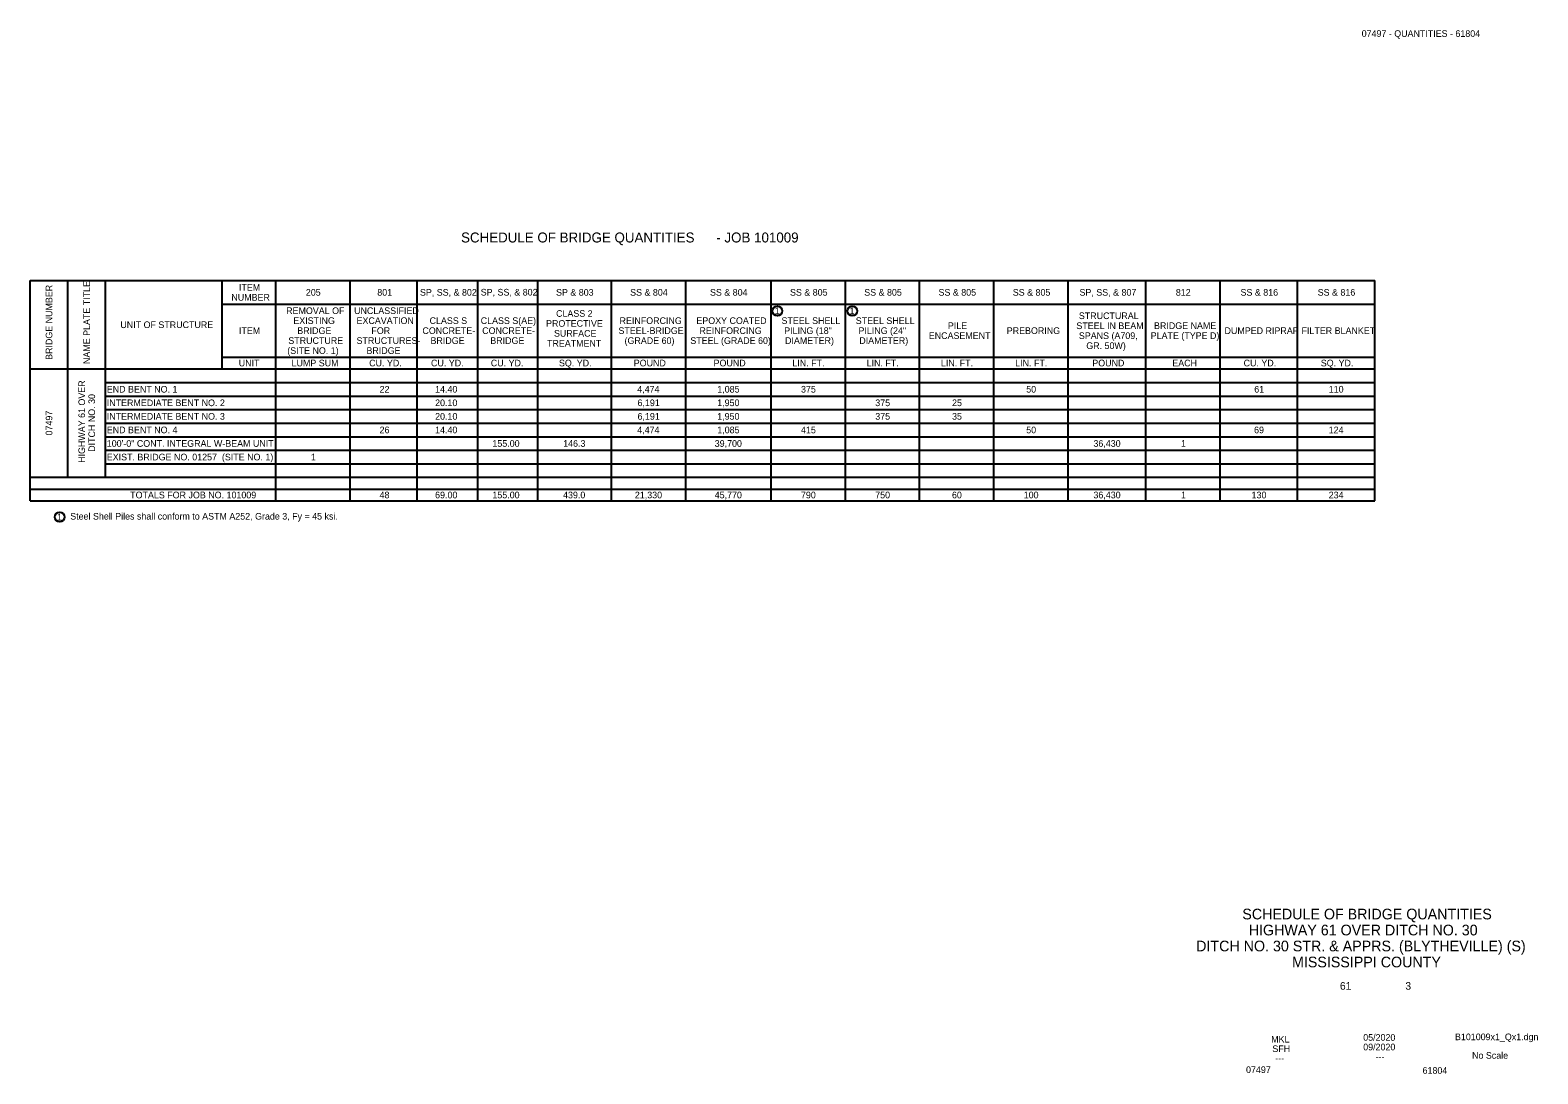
# Model space of a CAD drawing. Extents: x 192.8 to 249.4, y 129.2 to 148.9.
# Drawn here: x 192.85 to 221.19, y 129.23 to 148.86 of the extents above; entities that cross this region are included whole.
import ezdxf

# ---------------------------------------------------------------- set-up
doc = ezdxf.new("R2010")
doc.units = 0
for name, color, linetype in [('B_Copy In', 7, 'Continuous'), ('B_Dimensions', 7, 'Continuous'), ('B_Text', 7, 'Continuous'), ('B_Title Text', 7, 'Continuous')]:
    doc.layers.add(name, color=color, linetype=linetype)

msp = doc.modelspace()

# ---------------------------------------------------------------- linework, layer by layer
at = {"layer": 'B_Dimensions'}
msp.add_line((192.847, 144.151), (192.847, 144.151), dxfattribs=at)
at = {"layer": 'B_Text'}
for p, q in [((192.847, 144.151), (218.121, 144.151)), ((192.847, 140.007), (192.847, 144.151)), ((193.556, 140.451), (193.556, 144.151)), ((194.265, 140.451), (194.265, 144.151)), ((196.459, 142.489), (196.459, 144.151)), ((197.467, 140.007), (197.467, 144.151)), ((198.863, 140.007), (198.863, 144.151)), ((200.123, 140.007), (200.123, 144.151)), ((201.264, 140.007), (201.264, 144.151)), ((202.392, 140.007), (202.392, 144.151)), ((203.773, 140.007), (203.773, 144.151)), ((205.169, 140.007), (205.169, 144.151)), ((206.775, 140.007), (206.775, 144.151)), ((208.171, 140.007), (208.171, 144.151)), ((209.567, 140.007), (209.567, 144.151)), ((210.964, 140.007), (210.964, 144.151)), ((212.36, 140.007), (212.36, 144.151)), ((213.822, 140.007), (213.822, 144.151)), ((215.218, 140.007), (215.218, 144.151)), ((216.67, 140.007), (216.67, 144.151)), ((218.121, 140.007), (218.121, 144.151)), ((196.459, 143.708), (218.121, 143.708)), ((196.459, 142.711), (218.121, 142.711)), ((192.847, 142.489), (218.121, 142.489)), ((194.265, 142.234), (218.121, 142.234)), ((194.265, 141.98), (218.121, 141.98)), ((194.265, 141.725), (218.121, 141.725)), ((194.265, 141.47), (218.121, 141.47)), ((194.265, 141.215), (218.121, 141.215)), ((194.265, 140.96), (218.121, 140.96)), ((194.265, 140.705), (218.121, 140.705)), ((192.847, 140.451), (218.121, 140.451)), ((192.847, 140.229), (218.121, 140.229)), ((192.847, 140.007), (218.121, 140.007))]:
    msp.add_line(p, q, dxfattribs=at)
for centre in [(206.894, 143.581), (208.3, 143.581), (193.403, 139.703)]:
    msp.add_circle(centre, 0.0914, dxfattribs=at)

# ---------------------------------------------------------------- texts
at = {"layer": 'B_Copy In'}
for s, height, p in [('07497 - QUANTITIES - 61804', 0.1248, (217.877, 148.735)), ('SCHEDULE OF BRIDGE QUANTITIES', 0.2004, (215.633, 132.137)), ('HIGHWAY 61 OVER DITCH NO. 30', 0.2004, (215.753, 131.836)), ('DITCH NO. 30 STR. & APPRS. (BLYTHEVILLE) (S)', 0.2004, (214.765, 131.536)), ('MISSISSIPPI COUNTY', 0.2004, (216.567, 131.235)), ('MKL', 0.1248, (216.176, 129.821)), ('05/2020', 0.1248, (217.906, 129.854)), ('09/2020', 0.1248, (217.906, 129.674)), ('B101009x1_Qx1.dgn', 0.1248, (219.631, 129.865)), ('SFH', 0.1248, (216.198, 129.641)), ('---', 0.1248, (218.139, 129.487)), ('No Scale', 0.1248, (219.952, 129.516)), ('07497', 0.125, (215.703, 129.247)), ('---', 0.1248, (216.252, 129.461)), ('61804', 0.125, (219.021, 129.233))]:
    msp.add_text(s, height=height, dxfattribs=at).set_placement(p)
at = {"layer": 'B_Text'}
for s, height, p in [('SCHEDULE OF BRIDGE QUANTITIES', 0.1875, (200.947, 144.868)), (' - JOB 101009', 0.1875, (205.675, 144.868)), ('ITEM', 0.125, (196.772, 143.961)), ('205', 0.125, (198.029, 143.867)), ('801', 0.125, (199.372, 143.867)), ('SP, SS, & 802', 0.125, (200.174, 143.867)), ('SP, SS, & 802', 0.125, (201.316, 143.87)), ('SP & 803', 0.125, (202.732, 143.867)), ('SS & 804', 0.125, (204.125, 143.867)), ('SS & 804', 0.125, (205.626, 143.867)), ('SS & 805', 0.125, (207.13, 143.867)), ('SS & 805', 0.125, (208.526, 143.867)), ('SS & 805', 0.125, (209.922, 143.867)), ('SS & 805', 0.125, (211.318, 143.867)), ('SP, SS, & 807', 0.125, (212.572, 143.867)), ('812', 0.125, (214.383, 143.867)), ('SS & 816', 0.125, (215.599, 143.867)), ('SS & 816', 0.125, (217.05, 143.867)), ('NUMBER', 0.125, (196.629, 143.773)), ('REMOVAL OF', 0.125, (197.659, 143.522)), ('EXISTING', 0.125, (197.794, 143.335)), ('UNCLASSIFIED', 0.125, (198.936, 143.522)), (' EXCAVATION', 0.125, (198.936, 143.335)), ('CLASS S', 0.125, (200.355, 143.335)), ('CLASS S(AE)', 0.125, (201.316, 143.335)), ('PROTECTIVE', 0.1248, (202.545, 143.283)), ('CLASS 2', 0.1248, (202.733, 143.47)), ('REINFORCING', 0.125, (203.926, 143.335)), ('EPOXY COATED', 0.125, (205.371, 143.335)), ('1', 0.125, (206.844, 143.519)), ('STEEL SHELL', 0.125, (206.97, 143.335)), ('1', 0.125, (208.249, 143.519)), ('STEEL SHELL', 0.125, (208.366, 143.335)), (' STRUCTURAL', 0.125, (212.514, 143.427)), ('UNIT OF STRUCTURE', 0.125, (194.542, 143.258)), ('ITEM', 0.125, (196.772, 143.147)), ('BRIDGE', 0.125, (197.868, 143.147)), ('       FOR', 0.125, (198.936, 143.147)), ('CONCRETE-', 0.125, (200.22, 143.147)), ('CONCRETE-', 0.125, (201.344, 143.147)), ('SURFACE', 0.1248, (202.694, 143.096)), ('STEEL-BRIDGE', 0.125, (203.905, 143.147)), ('REINFORCING', 0.125, (205.428, 143.147)), ('PILING (18"', 0.125, (207.021, 143.147)), ('PILING (24"', 0.125, (208.417, 143.147)), ('ENCASEMENT', 0.125, (209.739, 143.053)), ('PILE', 0.125, (210.098, 143.241)), ('PREBORING', 0.125, (211.205, 143.147)), ('STEEL IN BEAM', 0.125, (212.514, 143.239)), (' SPANS (A709,', 0.125, (212.514, 143.052)), ('PLATE (TYPE D)', 0.125, (213.911, 143.053)), ('BRIDGE NAME', 0.125, (213.973, 143.241)), ('DUMPED RIPRAP', 0.125, (215.299, 143.147)), ('FILTER BLANKET', 0.125, (216.746, 143.147)), ('(SITE NO. 1)', 0.125, (197.68, 142.772)), ('STRUCTURE', 0.125, (197.7, 142.96)), (' STRUCTURES-', 0.125, (198.936, 142.96)), ('     BRIDGE', 0.125, (198.936, 142.772)), ('BRIDGE', 0.125, (200.372, 142.96)), ('BRIDGE', 0.125, (201.496, 142.96)), ('TREATMENT', 0.1248, (202.563, 142.909)), ('(GRADE 60)', 0.125, (204.02, 142.96)), ('STEEL (GRADE 60)', 0.125, (205.257, 142.96)), ('DIAMETER)', 0.125, (207.037, 142.96)), ('DIAMETER)', 0.125, (208.433, 142.96)), ('    GR. 50W)', 0.125, (212.514, 142.864)), ('UNIT', 0.125, (196.767, 142.538)), ('LUMP SUM', 0.125, (197.761, 142.538)), ('CU. YD.', 0.125, (199.219, 142.538)), ('CU. YD.', 0.125, (200.382, 142.538)), ('CU. YD.', 0.125, (201.506, 142.538)), ('SQ. YD.', 0.125, (202.787, 142.538)), ('POUND', 0.125, (204.193, 142.538)), ('POUND', 0.125, (205.694, 142.538)), ('LIN. FT.', 0.125, (207.175, 142.538)), ('LIN. FT.', 0.125, (208.571, 142.538)), ('LIN. FT.', 0.125, (209.967, 142.538)), ('LIN. FT.', 0.125, (211.363, 142.538)), ('POUND', 0.125, (212.813, 142.538)), ('EACH', 0.125, (214.317, 142.538)), ('CU. YD.', 0.125, (215.657, 142.538)), ('SQ. YD.', 0.125, (217.108, 142.538)), ('END BENT NO. 1', 0.125, (194.287, 142.045)), ('22', 0.125, (199.416, 142.045)), ('14.40', 0.125, (200.459, 142.045)), ('4,474', 0.125, (204.259, 142.045)), ('1,085', 0.125, (205.763, 142.045)), ('375', 0.125, (207.337, 142.045)), ('50', 0.125, (211.571, 142.045)), ('61', 0.125, (215.857, 142.045)), ('110', 0.125, (217.258, 142.045)), ('INTERMEDIATE BENT NO. 2', 0.125, (194.287, 141.79)), ('20.10', 0.125, (200.459, 141.79)), ('6,191', 0.125, (204.264, 141.79)), ('1,950', 0.125, (205.762, 141.79)), ('375', 0.125, (208.733, 141.79)), ('25', 0.125, (210.176, 141.79)), ('INTERMEDIATE BENT NO. 3', 0.125, (194.287, 141.535)), ('20.10', 0.125, (200.459, 141.535)), ('6,191', 0.125, (204.264, 141.535)), ('1,950', 0.125, (205.762, 141.535)), ('375', 0.125, (208.733, 141.535)), ('35', 0.125, (210.176, 141.535)), ('100\'-0" CONT. INTEGRAL W-BEAM UNIT', 0.125, (194.287, 141.025)), ('END BENT NO. 4', 0.125, (194.287, 141.28)), ('26', 0.125, (199.415, 141.28)), ('14.40', 0.125, (200.459, 141.28)), ('155.00', 0.125, (201.536, 141.025)), ('146.3', 0.125, (202.866, 141.025)), ('4,474', 0.125, (204.259, 141.28)), ('39,700', 0.125, (205.715, 141.025)), ('1,085', 0.125, (205.763, 141.28)), ('415', 0.125, (207.337, 141.28)), ('50', 0.125, (211.571, 141.28)), ('36,430', 0.125, (212.834, 141.025)), ('1', 0.125, (214.48, 141.025)), ('69', 0.125, (215.854, 141.28)), ('124', 0.125, (217.257, 141.28)), ('EXIST. BRIDGE NO. 01257  (SITE NO. 1)', 0.125, (194.287, 140.77)), ('1', 0.125, (198.125, 140.77)), ('TOTALS FOR JOB NO. 101009', 0.125, (194.727, 140.056)), ('48', 0.125, (199.415, 140.056)), ('69.00', 0.125, (200.459, 140.056)), ('155.00', 0.125, (201.536, 140.056)), ('439.0', 0.125, (202.864, 140.056)), ('21,330', 0.125, (204.214, 140.056)), ('45,770', 0.125, (205.715, 140.056)), ('790', 0.125, (207.336, 140.056)), ('750', 0.125, (208.732, 140.056)), ('60', 0.125, (210.175, 140.056)), ('100', 0.125, (211.524, 140.056)), ('36,430', 0.125, (212.834, 140.056)), ('1', 0.125, (214.48, 140.056)), ('130', 0.125, (215.807, 140.056)), ('234', 0.125, (217.257, 140.056)), ('1', 0.125, (193.352, 139.64)), ('Steel Shell Piles shall conform to ASTM A252, Grade 3, Fy = 45 ksi.', 0.125, (193.6, 139.656))]:
    msp.add_text(s, height=height, dxfattribs=at).set_placement(p)
for s, p in [('BRIDGE NUMBER', (193.264, 142.66)), ('NAME PLATE TITLE', (193.973, 142.582)), ('HIGHWAY 61 OVER', (193.879, 140.723)), ('DITCH NO. 30', (194.067, 140.931)), ('07497', (193.264, 141.239))]:
    msp.add_text(s, height=0.125, rotation=90, dxfattribs=at).set_placement(p)
at = {"layer": 'B_Title Text'}
msp.add_text('61                   3', height=0.144, dxfattribs=at).set_placement((217.468, 130.814))

doc.saveas('drawing.dxf')
